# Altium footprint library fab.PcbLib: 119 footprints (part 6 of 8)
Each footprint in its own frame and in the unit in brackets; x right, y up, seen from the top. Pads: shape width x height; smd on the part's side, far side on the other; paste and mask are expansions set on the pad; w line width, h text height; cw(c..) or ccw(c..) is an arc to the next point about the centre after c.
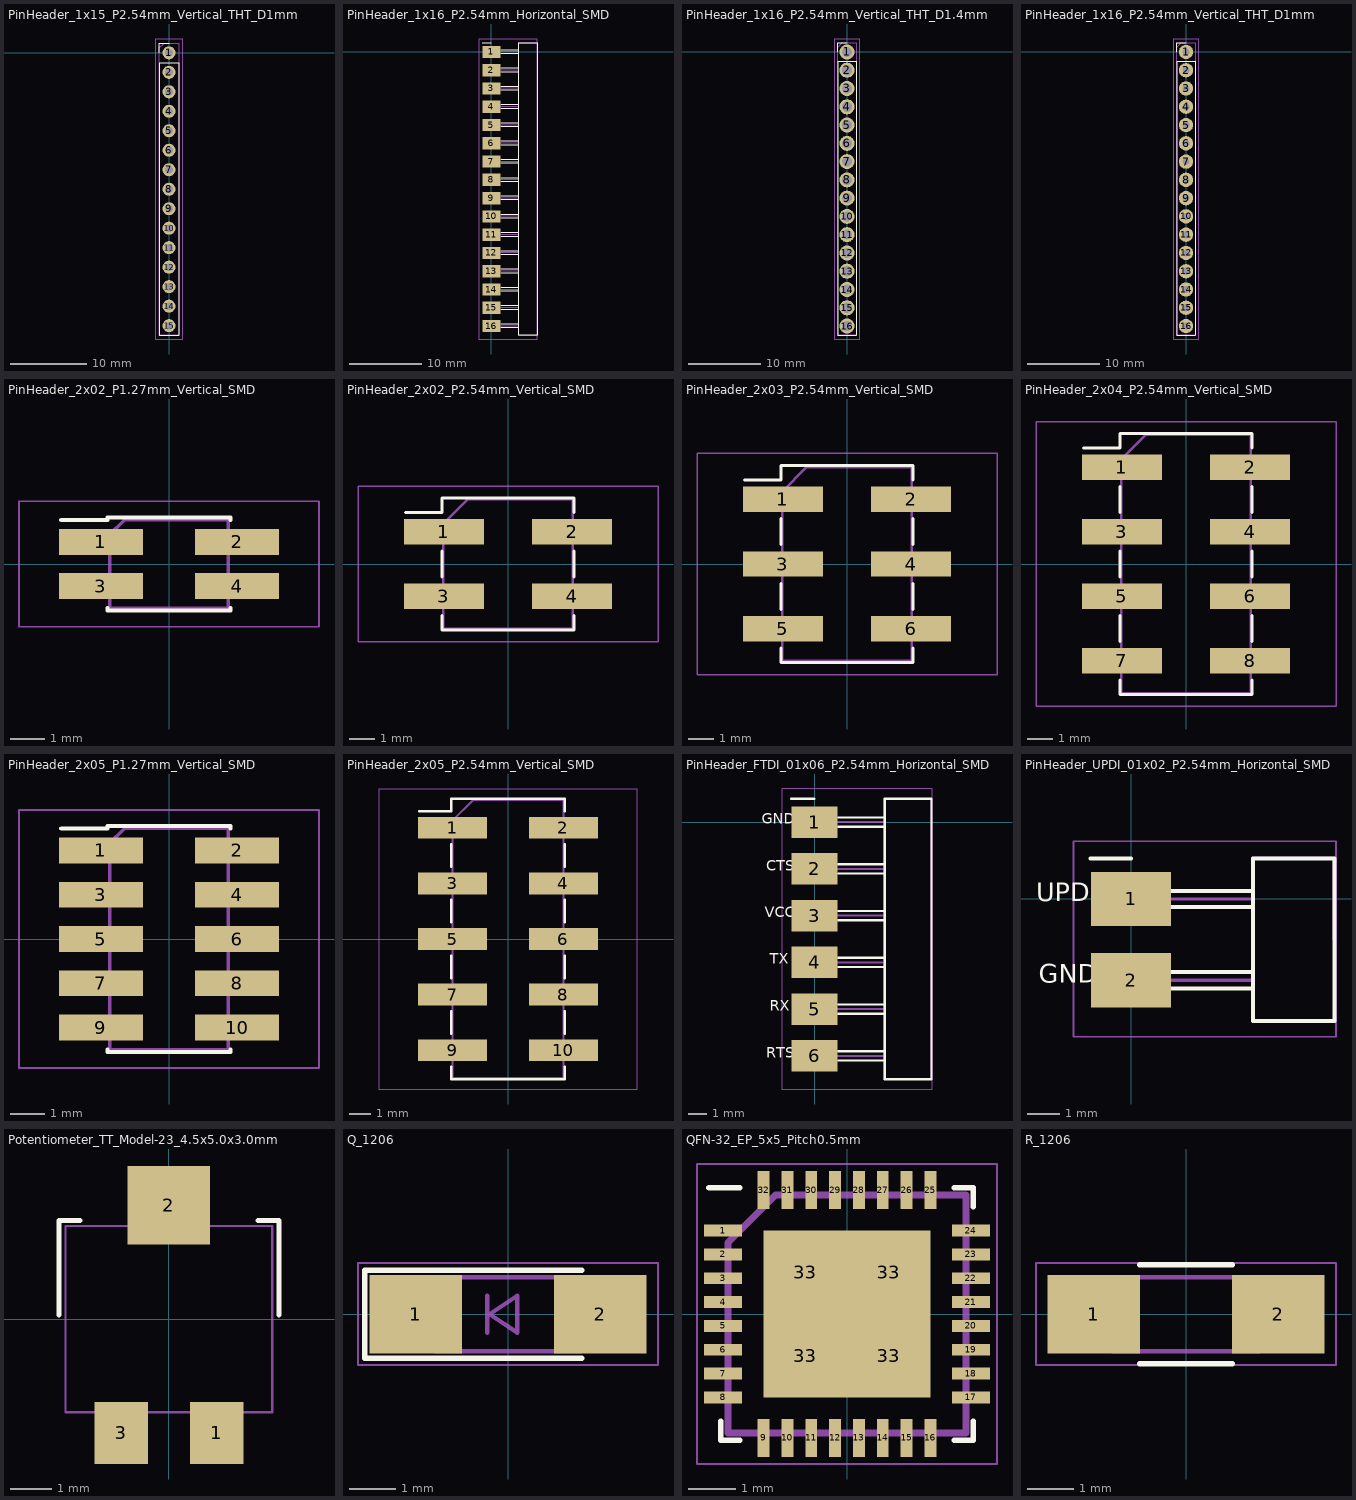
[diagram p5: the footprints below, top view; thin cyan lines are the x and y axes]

## PinHeader_1x15_P2.54mm_Vertical_THT_D1mm [mm]
pads (15):
  round 1.7 hole 1: 1(0,0)
  rrect100% 1.7x1.7 hole 1: 2(0,-2.54) 3(0,-5.08) 4(0,-7.62) 5(0,-10.16) 6(0,-12.7) 7(0,-15.24) 8(0,-17.78) 9(0,-20.32) 10(0,-22.86) 11(0,-25.4) 12(0,-27.94) 13(0,-30.48) 14(0,-33.02) 15(0,-35.56)
F.SilkS:
  lines w0.12: -1.27,0 -1.27,1.27 0,1.27 ; -1.27,-36.83 -1.27,-1.27 1.27,-1.27 1.27,-36.83 -1.27,-36.83
F.CrtYd:
  lines w0.05: -1.8,-37.3 1.8,-37.3 1.8,1.8 -1.8,1.8 -1.8,-37.3
F.Fab:
  lines w0.1: -1.27,-36.83 -1.27,0.635 -0.635,1.27 1.27,1.27 1.27,-36.83 -1.27,-36.83
  text "%R" at 0.294,-9.283 h1

## PinHeader_1x16_P2.54mm_Horizontal_SMD [mm]
pads (16):
  rect 2.5x1.7 smd: 1(0,0) 2(0,-2.54) 3(0,-5.08) 4(0,-7.62) 5(0,-10.16) 6(0,-12.7) 7(0,-15.24) 8(0,-17.78) 9(0,-20.32) 10(0,-22.86) 11(0,-25.4) 12(0,-27.94) 13(0,-30.48) 14(0,-33.02) 15(0,-35.56) 16(0,-38.1)
F.SilkS:
  lines w0.12: -1.27,1.27 0,1.27 ; 1.27,-38.354 3.81,-38.354 ; 1.27,-37.846 3.81,-37.846 ; 1.27,-35.814 3.81,-35.814 ; 1.27,-35.306 3.81,-35.306 ; 1.27,-33.274 3.81,-33.274 ; 1.27,-32.766 3.81,-32.766 ; 1.27,-30.734 3.81,-30.734 ; 1.27,-30.226 3.81,-30.226 ; 1.27,-28.194 3.81,-28.194 ; 1.27,-27.686 3.81,-27.686 ; 1.27,-25.654 3.81,-25.654 ; 1.27,-25.146 3.81,-25.146 ; 1.27,-23.114 3.81,-23.114 ; 1.27,-22.606 3.81,-22.606 ; 1.27,-20.574 3.81,-20.574 ; 1.27,-20.066 3.81,-20.066 ; 1.27,-18.034 3.81,-18.034 ; 1.27,-17.526 3.81,-17.526 ; 1.27,-15.494 3.81,-15.494 ; 1.27,-14.986 3.81,-14.986 ; 1.27,-12.954 3.81,-12.954 ; 1.27,-12.446 3.81,-12.446 ; 1.27,-10.414 3.81,-10.414 ; 1.27,-9.906 3.81,-9.906 ; 1.27,-7.874 3.81,-7.874 ; 1.27,-7.366 3.81,-7.366 ; 1.27,-5.334 3.81,-5.334 ; 1.27,-4.826 3.81,-4.826 ; 1.27,-2.794 3.81,-2.794 ; 1.27,-2.286 3.81,-2.286 ; 1.27,-0.254 3.81,-0.254 ; 1.27,0.254 3.81,0.254 ; 3.81,-39.37 6.35,-39.37 6.35,1.27 3.81,1.27 3.81,-39.37
F.CrtYd:
  lines w0.05: -1.8,-39.9 6.4,-39.9 6.4,1.8 -1.8,1.8 -1.8,-39.9
F.Fab:
  lines w0.1: -0.635,-38.1 3.81,-38.1 ; -0.635,-35.56 3.81,-35.56 ; -0.635,-33.02 3.81,-33.02 ; -0.635,-30.48 3.81,-30.48 ; -0.635,-27.94 3.81,-27.94 ; -0.635,-25.4 3.81,-25.4 ; -0.635,-23.114 -0.635,-22.606 ; -0.635,-22.86 3.81,-22.86 ; -0.635,-20.574 -0.635,-20.066 ; -0.635,-20.32 3.81,-20.32 ; -0.635,-18.034 -0.635,-17.526 ; -0.635,-17.78 3.81,-17.78 ; -0.635,-15.494 -0.635,-14.986 ; -0.635,-15.24 3.81,-15.24 ; -0.635,-12.954 -0.635,-12.446 ; -0.635,-12.7 3.81,-12.7 ; -0.635,-10.414 -0.635,-9.906 ; -0.635,-10.16 3.81,-10.16 ; -0.635,-7.874 -0.635,-7.366 ; -0.635,-7.62 3.81,-7.62 ; -0.635,-5.334 -0.635,-4.826 ; -0.635,-5.08 3.81,-5.08 ; -0.635,-2.794 -0.635,-2.286 ; -0.635,-2.54 3.81,-2.54 ; -0.635,-0.254 -0.635,0.254 ; -0.635,0 3.81,0 ; 3.8,-39.37 6.35,-39.37 6.34,1.27 3.8,1.27 3.81,-39.37
  text "%R" at 2.834,-19.443 h1

## PinHeader_1x16_P2.54mm_Vertical_THT_D1.4mm [mm]
pads (16):
  round 2.1 hole 1.4: 1(0,0) 2(0,-2.54) 3(0,-5.08) 4(0,-7.62) 5(0,-10.16) 6(0,-12.7) 7(0,-15.24) 8(0,-17.78) 9(0,-20.32) 10(0,-22.86) 11(0,-25.4) 12(0,-27.94) 13(0,-30.48) 14(0,-33.02) 15(0,-35.56) 16(0,-38.1)
F.SilkS:
  lines w0.12: -1.27,0 -1.27,1.27 0,1.27 ; -1.27,-39.37 1.27,-39.37 1.27,-1.27 -1.27,-1.27 -1.27,-39.37
F.CrtYd:
  lines w0.05: -1.8,-39.9 -1.8,1.8 1.8,1.8 1.8,-39.9 -1.8,-39.9
F.Fab:
  lines w0.1: -1.27,-39.37 1.27,-39.37 1.27,1.27 -0.635,1.27 -1.27,0.635 -1.27,-39.37
  text "%R" at 0.294,-9.283 h1

## PinHeader_1x16_P2.54mm_Vertical_THT_D1mm [mm]
pads (16):
  round 2 hole 1: 1(0,0)
  rrect100% 2x2 hole 1: 2(0,-2.54) 3(0,-5.08) 4(0,-7.62) 5(0,-10.16) 6(0,-12.7) 7(0,-15.24) 8(0,-17.78) 9(0,-20.32) 10(0,-22.86) 11(0,-25.4) 12(0,-27.94) 13(0,-30.48) 14(0,-33.02) 15(0,-35.56) 16(0,-38.1)
F.SilkS:
  lines w0.12: -1.27,0 -1.27,1.27 0,1.27 ; -1.27,-39.37 -1.27,-1.27 1.27,-1.27 1.27,-39.37 -1.27,-39.37
F.CrtYd:
  lines w0.05: -1.8,-39.9 1.8,-39.9 1.8,1.8 -1.8,1.8 -1.8,-39.9
F.Fab:
  lines w0.1: -1.27,-39.37 -1.27,0.635 -0.635,1.27 1.27,1.27 1.27,-39.37 -1.27,-39.37
  text "%R" at 0.294,-9.283 h1

## PinHeader_2x02_P1.27mm_Vertical_SMD [mm]
pads (4):
  rect 2.4x0.74 smd: 1(-1.95,0.635) 2(1.95,0.635) 3(-1.95,-0.635) 4(1.95,-0.635)
F.SilkS:
  lines w0.12: -3.09,1.265 -1.765,1.265 -1.765,1.33 1.765,1.33 1.765,1.265 ; -1.765,-1.265 -1.765,-1.33 1.765,-1.33 1.765,-1.265
F.CrtYd:
  lines w0.05: -4.3,-1.8 -4.3,1.8 4.3,1.8 4.3,-1.8 -4.3,-1.8
F.Fab:
  lines w0.1: -1.705,-0.835 -2.75,-0.835 -2.75,-0.435 -1.705,-0.435 ; -1.705,0.435 -2.75,0.435 -2.75,0.835 -1.705,0.835 ; 1.705,-0.835 2.75,-0.835 2.75,-0.435 1.705,-0.435 ; 1.705,0.435 2.75,0.435 2.75,0.835 1.705,0.835 ; -1.705,0.835 -1.705,-1.27 1.705,-1.27 1.705,1.27 -1.27,1.27 -1.705,0.835
  text "%R" at 0.294,-0.393 h1

## PinHeader_2x02_P2.54mm_Vertical_SMD [mm]
pads (4):
  rect 3.15x1 smd: 1(-2.525,1.27) 2(2.525,1.27) 3(-2.525,-1.27) 4(2.525,-1.27)
F.SilkS:
  lines w0.12: -4.04,2.03 -2.6,2.03 -2.6,2.6 2.6,2.6 2.6,2.03 ; -2.6,-2.03 -2.6,-2.6 2.6,-2.6 2.6,-2.03 ; -2.6,-0.51 -2.6,0.51 ; 2.6,-0.51 2.6,0.51
F.CrtYd:
  lines w0.05: -5.9,-3.05 5.9,-3.05 5.9,3.05 -5.9,3.05 -5.9,-3.05
F.Fab:
  lines w0.1: -2.54,-1.59 -3.6,-1.59 -3.6,-0.95 -2.54,-0.95 ; -2.54,0.95 -3.6,0.95 -3.6,1.59 -2.54,1.59 ; 2.54,-1.59 3.6,-1.59 3.6,-0.95 2.54,-0.95 ; 2.54,0.95 3.6,0.95 3.6,1.59 2.54,1.59 ; -2.54,1.59 -1.59,2.54 2.54,2.54 2.54,-2.54 -2.54,-2.54 -2.54,1.59
  text "%R" at 0.294,-0.393 h1

## PinHeader_2x03_P2.54mm_Vertical_SMD [mm]
pads (6):
  rect 3.15x1 smd: 1(-2.525,2.54) 2(2.525,2.54) 3(-2.525,0) 4(2.525,0) 5(-2.525,-2.54) 6(2.525,-2.54)
F.SilkS:
  lines w0.12: -4.04,3.3 -2.6,3.3 -2.6,3.87 2.6,3.87 2.6,3.3 ; -2.6,-3.3 -2.6,-3.87 2.6,-3.87 2.6,-3.3 ; -2.6,-1.78 -2.6,-0.76 ; -2.6,0.76 -2.6,1.78 ; 2.6,-1.78 2.6,-0.76 ; 2.6,0.76 2.6,1.78
F.CrtYd:
  lines w0.05: -5.9,-4.35 -5.9,4.35 5.9,4.35 5.9,-4.35 -5.9,-4.35
F.Fab:
  lines w0.1: -2.54,-2.86 -3.6,-2.86 -3.6,-2.22 -2.54,-2.22 ; -2.54,-0.32 -3.6,-0.32 -3.6,0.32 -2.54,0.32 ; -2.54,2.22 -3.6,2.22 -3.6,2.86 -2.54,2.86 ; 2.54,-2.86 3.6,-2.86 3.6,-2.22 2.54,-2.22 ; 2.54,-0.32 3.6,-0.32 3.6,0.32 2.54,0.32 ; 2.54,2.22 3.6,2.22 3.6,2.86 2.54,2.86 ; -2.54,2.86 -2.54,-3.81 2.54,-3.81 2.54,3.81 -1.59,3.81 -2.54,2.86
  text "%R" at 0.294,-0.393 h1

## PinHeader_2x04_P2.54mm_Vertical_SMD [mm]
pads (8):
  rect 3.15x1 smd: 1(-2.525,3.81) 2(2.525,3.81) 3(-2.525,1.27) 4(2.525,1.27) 5(-2.525,-1.27) 6(2.525,-1.27) 7(-2.525,-3.81) 8(2.525,-3.81)
F.SilkS:
  lines w0.12: -4.04,4.57 -2.6,4.57 -2.6,5.14 2.6,5.14 2.6,4.57 ; -2.6,-4.57 -2.6,-5.14 2.6,-5.14 2.6,-4.57 ; -2.6,-3.05 -2.6,-2.03 ; -2.6,-0.51 -2.6,0.51 ; -2.6,2.03 -2.6,3.05 ; 2.6,-3.05 2.6,-2.03 ; 2.6,-0.51 2.6,0.51 ; 2.6,2.03 2.6,3.05
F.CrtYd:
  lines w0.05: -5.9,-5.6 -5.9,5.6 5.9,5.6 5.9,-5.6 -5.9,-5.6
F.Fab:
  lines w0.1: -2.54,-4.13 -3.6,-4.13 -3.6,-3.49 -2.54,-3.49 ; -2.54,-1.59 -3.6,-1.59 -3.6,-0.95 -2.54,-0.95 ; -2.54,0.95 -3.6,0.95 -3.6,1.59 -2.54,1.59 ; -2.54,3.49 -3.6,3.49 -3.6,4.13 -2.54,4.13 ; 2.54,-4.13 3.6,-4.13 3.6,-3.49 2.54,-3.49 ; 2.54,-1.59 3.6,-1.59 3.6,-0.95 2.54,-0.95 ; 2.54,0.95 3.6,0.95 3.6,1.59 2.54,1.59 ; 2.54,3.49 3.6,3.49 3.6,4.13 2.54,4.13 ; -2.54,4.13 -2.54,-5.08 2.54,-5.08 2.54,5.08 -1.59,5.08 -2.54,4.13
  text "%R" at 0.294,-0.393 h1

## PinHeader_2x05_P1.27mm_Vertical_SMD [mm]
pads (10):
  rect 2.4x0.74 smd: 1(-1.95,2.54) 2(1.95,2.54) 3(-1.95,1.27) 4(1.95,1.27) 5(-1.95,0) 6(1.95,0) 7(-1.95,-1.27) 8(1.95,-1.27) 9(-1.95,-2.54) 10(1.95,-2.54)
F.SilkS:
  lines w0.12: -3.09,3.17 -1.765,3.17 -1.765,3.235 1.765,3.235 1.765,3.17 ; -1.765,-3.17 -1.765,-3.235 1.765,-3.235 1.765,-3.17
F.CrtYd:
  lines w0.05: -4.3,-3.7 -4.3,3.7 4.3,3.7 4.3,-3.7 -4.3,-3.7
F.Fab:
  lines w0.1: -1.705,-2.74 -2.75,-2.74 -2.75,-2.34 -1.705,-2.34 ; -1.705,-1.47 -2.75,-1.47 -2.75,-1.07 -1.705,-1.07 ; -1.705,-0.2 -2.75,-0.2 -2.75,0.2 -1.705,0.2 ; -1.705,1.07 -2.75,1.07 -2.75,1.47 -1.705,1.47 ; -1.705,2.34 -2.75,2.34 -2.75,2.74 -1.705,2.74 ; 1.705,-2.74 2.75,-2.74 2.75,-2.34 1.705,-2.34 ; 1.705,-1.47 2.75,-1.47 2.75,-1.07 1.705,-1.07 ; 1.705,-0.2 2.75,-0.2 2.75,0.2 1.705,0.2 ; 1.705,1.07 2.75,1.07 2.75,1.47 1.705,1.47 ; 1.705,2.34 2.75,2.34 2.75,2.74 1.705,2.74 ; -1.705,2.74 -1.705,-3.175 1.705,-3.175 1.705,3.175 -1.27,3.175 -1.705,2.74
  text "%R" at 0.294,-0.393 h1

## PinHeader_2x05_P2.54mm_Vertical_SMD [mm]
pads (10):
  rect 3.15x1 smd: 1(-2.525,5.08) 2(2.525,5.08) 3(-2.525,2.54) 4(2.525,2.54) 5(-2.525,0) 6(2.525,0) 7(-2.525,-2.54) 8(2.525,-2.54) 9(-2.525,-5.08) 10(2.525,-5.08)
F.SilkS:
  lines w0.12: -4.04,5.84 -2.6,5.84 -2.6,6.41 2.6,6.41 2.6,5.84 ; -2.6,-5.84 -2.6,-6.41 2.6,-6.41 2.6,-5.84 ; -2.6,-4.32 -2.6,-3.3 ; -2.6,-1.78 -2.6,-0.76 ; -2.6,0.76 -2.6,1.78 ; -2.6,3.3 -2.6,4.32 ; 2.6,-4.32 2.6,-3.3 ; 2.6,-1.78 2.6,-0.76 ; 2.6,0.76 2.6,1.78 ; 2.6,3.3 2.6,4.32
F.CrtYd:
  lines w0.05: -5.9,-6.85 -5.9,6.85 5.9,6.85 5.9,-6.85 -5.9,-6.85
F.Fab:
  lines w0.1: -2.54,-5.4 -3.6,-5.4 -3.6,-4.76 -2.54,-4.76 ; -2.54,-2.86 -3.6,-2.86 -3.6,-2.22 -2.54,-2.22 ; -2.54,-0.32 -3.6,-0.32 -3.6,0.32 -2.54,0.32 ; -2.54,2.22 -3.6,2.22 -3.6,2.86 -2.54,2.86 ; -2.54,4.76 -3.6,4.76 -3.6,5.4 -2.54,5.4 ; 2.54,-5.4 3.6,-5.4 3.6,-4.76 2.54,-4.76 ; 2.54,-2.86 3.6,-2.86 3.6,-2.22 2.54,-2.22 ; 2.54,-0.32 3.6,-0.32 3.6,0.32 2.54,0.32 ; 2.54,2.22 3.6,2.22 3.6,2.86 2.54,2.86 ; 2.54,4.76 3.6,4.76 3.6,5.4 2.54,5.4 ; -2.54,5.4 -2.54,-6.35 2.54,-6.35 2.54,6.35 -1.59,6.35 -2.54,5.4
  text "%R" at 0.294,-0.393 h1

## PinHeader_FTDI_01x06_P2.54mm_Horizontal_SMD [mm]
pads (6):
  rect 2.5x1.7 smd: 1(0,0) 2(0,-2.54) 3(0,-5.08) 4(0,-7.62) 5(0,-10.16) 6(0,-12.7)
F.SilkS:
  lines w0.12: -1.27,1.27 0,1.27 ; 1.27,-12.954 3.81,-12.954 ; 1.27,-12.446 3.81,-12.446 ; 1.27,-10.414 3.81,-10.414 ; 1.27,-9.906 3.81,-9.906 ; 1.27,-7.874 3.81,-7.874 ; 1.27,-7.366 3.81,-7.366 ; 1.27,-5.334 3.81,-5.334 ; 1.27,-4.826 3.81,-4.826 ; 1.27,-2.794 3.81,-2.794 ; 1.27,-2.286 3.81,-2.286 ; 1.27,-0.254 3.81,-0.254 ; 1.27,0.254 3.81,0.254 ; 3.81,-13.97 6.35,-13.97 6.35,1.27 3.81,1.27 3.81,-13.97
  text "GND" at -2.883,-0.285 h1
  text "CTS" at -2.627,-2.825 h1
  text "VCC" at -2.704,-5.365 h1
  text "TX" at -2.444,-7.897 h1
  text "RX" at -2.446,-10.437 h1
  text "RTS" at -2.63,-12.985 h1
F.CrtYd:
  lines w0.05: -1.8,-14.5 6.4,-14.5 6.4,1.8 -1.8,1.8 -1.8,-14.5
F.Fab:
  lines w0.1: -0.635,-12.954 -0.635,-12.446 ; -0.635,-12.7 3.81,-12.7 ; -0.635,-10.414 -0.635,-9.906 ; -0.635,-10.16 3.81,-10.16 ; -0.635,-7.874 -0.635,-7.366 ; -0.635,-7.62 3.81,-7.62 ; -0.635,-5.334 -0.635,-4.826 ; -0.635,-5.08 3.81,-5.08 ; -0.635,-2.794 -0.635,-2.286 ; -0.635,-2.54 3.81,-2.54 ; -0.635,-0.254 -0.635,0.254 ; -0.635,0 3.81,0 ; 3.8,-13.97 3.8,1.27 6.34,1.27 6.35,-13.97 3.8,-13.97
  text "%R" at 2.894,-6.493 h1

## PinHeader_UPDI_01x02_P2.54mm_Horizontal_SMD [mm]
pads (2):
  rect 2.5x1.7 smd: 1(0,0) 2(0,-2.54)
F.SilkS:
  lines w0.12: -1.27,1.27 0,1.27 ; 1.27,-2.794 3.81,-2.794 ; 1.27,-2.286 3.81,-2.286 ; 1.27,-0.254 3.81,-0.254 ; 1.27,0.254 3.81,0.254 ; 3.81,-3.81 6.35,-3.81 6.35,1.27 3.81,1.27 3.81,-3.81
  text "UPDI" at -2.972,-0.281 h1
  text "GND" at -2.883,-2.825 h1
F.CrtYd:
  lines w0.05: -1.8,-4.3 6.4,-4.3 6.4,1.8 -1.8,1.8 -1.8,-4.3
F.Fab:
  lines w0.1: -0.635,-2.794 -0.635,-2.286 ; -0.635,-2.54 3.81,-2.54 ; -0.635,-0.254 -0.635,0.254 ; -0.635,0 3.81,0 ; 3.8,-3.81 6.35,-3.81 6.34,1.27 3.8,1.27 3.81,-3.81
  text "%R" at 2.834,-1.663 h1

## Potentiometer_TT_Model-23_4.5x5.0x3.0mm [mm]
pads (3):
  rect 1.3x1.5 smd: 1(1.16,-2.75) 3(-1.15,-2.75)
  rect 2x1.9 smd: 2(0,2.75)
F.SilkS:
  lines w0.12: -2.65,0.1 -2.65,2.38 -2.14,2.38 ; 2.15,2.38 2.66,2.38 2.66,0.1
F.CrtYd:
  lines w0.05: -2.5,-2.25 -2.5,2.25 2.5,2.25 2.5,-2.25 -2.5,-2.25

## Q_1206 [mm]
pads (2):
  rect 2x1.7 smd: 1(-2,0) 2(2,0)
F.SilkS:
  lines w0.12: 1.6,-0.95 -3.1,-0.95 -3.1,0.95 1.6,0.95
F.CrtYd:
  lines w0.05: -3.25,-1.1 3.25,-1.1 3.25,1.11 -3.25,1.11 -3.25,-1.1
F.Fab:
  lines w0.1: -0.45,-0.4 -0.45,0.4 ; -1.6,-0.8 1.6,-0.8 1.6,0.8 -1.6,0.8 -1.6,-0.8 ; -0.4,0 0.2,-0.4 0.2,0.4 -0.4,0

## QFN-32_EP_5x5_Pitch0.5mm [mm]
pads (36):
  rect 0.8x0.25 smd: 1(-2.6,1.75) 2(-2.6,1.25) 3(-2.6,0.75) 4(-2.6,0.25) 5(-2.6,-0.25) 6(-2.6,-0.75) 7(-2.6,-1.25) 8(-2.6,-1.75) 17(2.6,-1.75) 18(2.6,-1.25) 19(2.6,-0.75) 20(2.6,-0.25) 21(2.6,0.25) 22(2.6,0.75) 23(2.6,1.25) 24(2.6,1.75)
  rect 0.25x0.8 smd: 9(-1.75,-2.6) 10(-1.25,-2.6) 11(-0.75,-2.6) 12(-0.25,-2.6) 13(0.25,-2.6) 14(0.75,-2.6) 15(1.25,-2.6) 16(1.75,-2.6) 25(1.75,2.6) 26(1.25,2.6) 27(0.75,2.6) 28(0.25,2.6) 29(-0.25,2.6) 30(-0.75,2.6) 31(-1.25,2.6) 32(-1.75,2.6)
  rect 1.75x1.75 smd: 33(-0.875,-0.875) 33(-0.875,0.875) 33(0.875,-0.875) 33(0.875,0.875)
F.SilkS:
  lines w0.12: -2.9,2.65 -2.25,2.65 ; -2.65,-2.25 -2.65,-2.65 -2.25,-2.65 ; 2.25,-2.65 2.65,-2.65 2.65,-2.25 ; 2.25,2.65 2.65,2.65 2.65,2.25
F.CrtYd:
  lines w0.05: -3.15,-3.15 3.15,-3.15 3.15,3.15 -3.15,3.15 -3.15,-3.15
F.Fab:
  lines w0.15: -2.5,-2.5 -2.5,1.5 -1.5,2.5 2.5,2.5 2.5,-2.5 -2.5,-2.5

## R_1206 [mm]
pads (2):
  rect 2x1.7 smd: 1(-2,0) 2(2,0)
F.SilkS:
  lines w0.12: -1,-1.07 1,-1.07 ; -1,1.07 1,1.07
F.CrtYd:
  lines w0.05: -3.25,-1.1 -3.25,1.11 3.25,1.11 3.25,-1.1 -3.25,-1.1
F.Fab:
  lines w0.1: -1.6,-0.8 -1.6,0.8 1.6,0.8 1.6,-0.8 -1.6,-0.8
  text "%R" at -0.275,-0.205 h0.7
